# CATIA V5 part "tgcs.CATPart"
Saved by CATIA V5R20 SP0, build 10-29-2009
Part number: TGCS
Revision: 9
Definition: design
Nomenclature: TGCS
Source: made
Description: NOT SPECIFIED
Bounding box of the stored display mesh (mm): x -2.55 to 13.3, y -3 to 13.309, z -16 to 2
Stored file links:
  C:\Users\Utente\Desktop\IO LAVORO\3D X SITO CF\X SITO\PLASTICA\TGC-XS\tgcs.CATPart
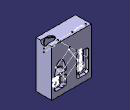
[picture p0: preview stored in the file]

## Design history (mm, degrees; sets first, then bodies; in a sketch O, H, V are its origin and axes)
Set1
  DatumCurve1 "COMPOSITE_CURVE #6304"
  Line1 "COMPOSITE_CURVE #6312": stored without definition
  DatumCurve2 "COMPOSITE_CURVE #6326"
  DatumCurve3 "COMPOSITE_CURVE #6345"
  DatumCurve4 "COMPOSITE_CURVE #6388"
  Line2 "COMPOSITE_CURVE #6395": stored without definition
  DatumCurve5 "COMPOSITE_CURVE #6420"
  Line3 "COMPOSITE_CURVE #6427": stored without definition
  Circle1 "COMPOSITE_CURVE #6442": stored without definition
  Circle2 "COMPOSITE_CURVE #6457": stored without definition
  DatumCurve6 "COMPOSITE_CURVE #6574"
  DatumCurve7 "COMPOSITE_CURVE #6738"
  DatumCurve8 "COMPOSITE_CURVE #6765"
  DatumCurve9 "COMPOSITE_CURVE #6792"
  DatumCurve10 "COMPOSITE_CURVE #6818"
  DatumCurve11 "COMPOSITE_CURVE #6843"
  DatumCurve12 "COMPOSITE_CURVE #6868"
  DatumCurve13 "COMPOSITE_CURVE #6922"
  DatumCurve14 "COMPOSITE_CURVE #7163"
  DatumCurve15 "COMPOSITE_CURVE #7488"
  Line4 "LINE #7492": stored without definition
  DatumSurface1 "OPEN_SHELL #6146"
  DatumSurface2 "OPEN_SHELL #6225"
Body1 "MANIFOLD_SOLID_BREP #6226" (main body)
  Solid1: solid without history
